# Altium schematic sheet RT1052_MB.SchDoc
size 297 x 210 mm
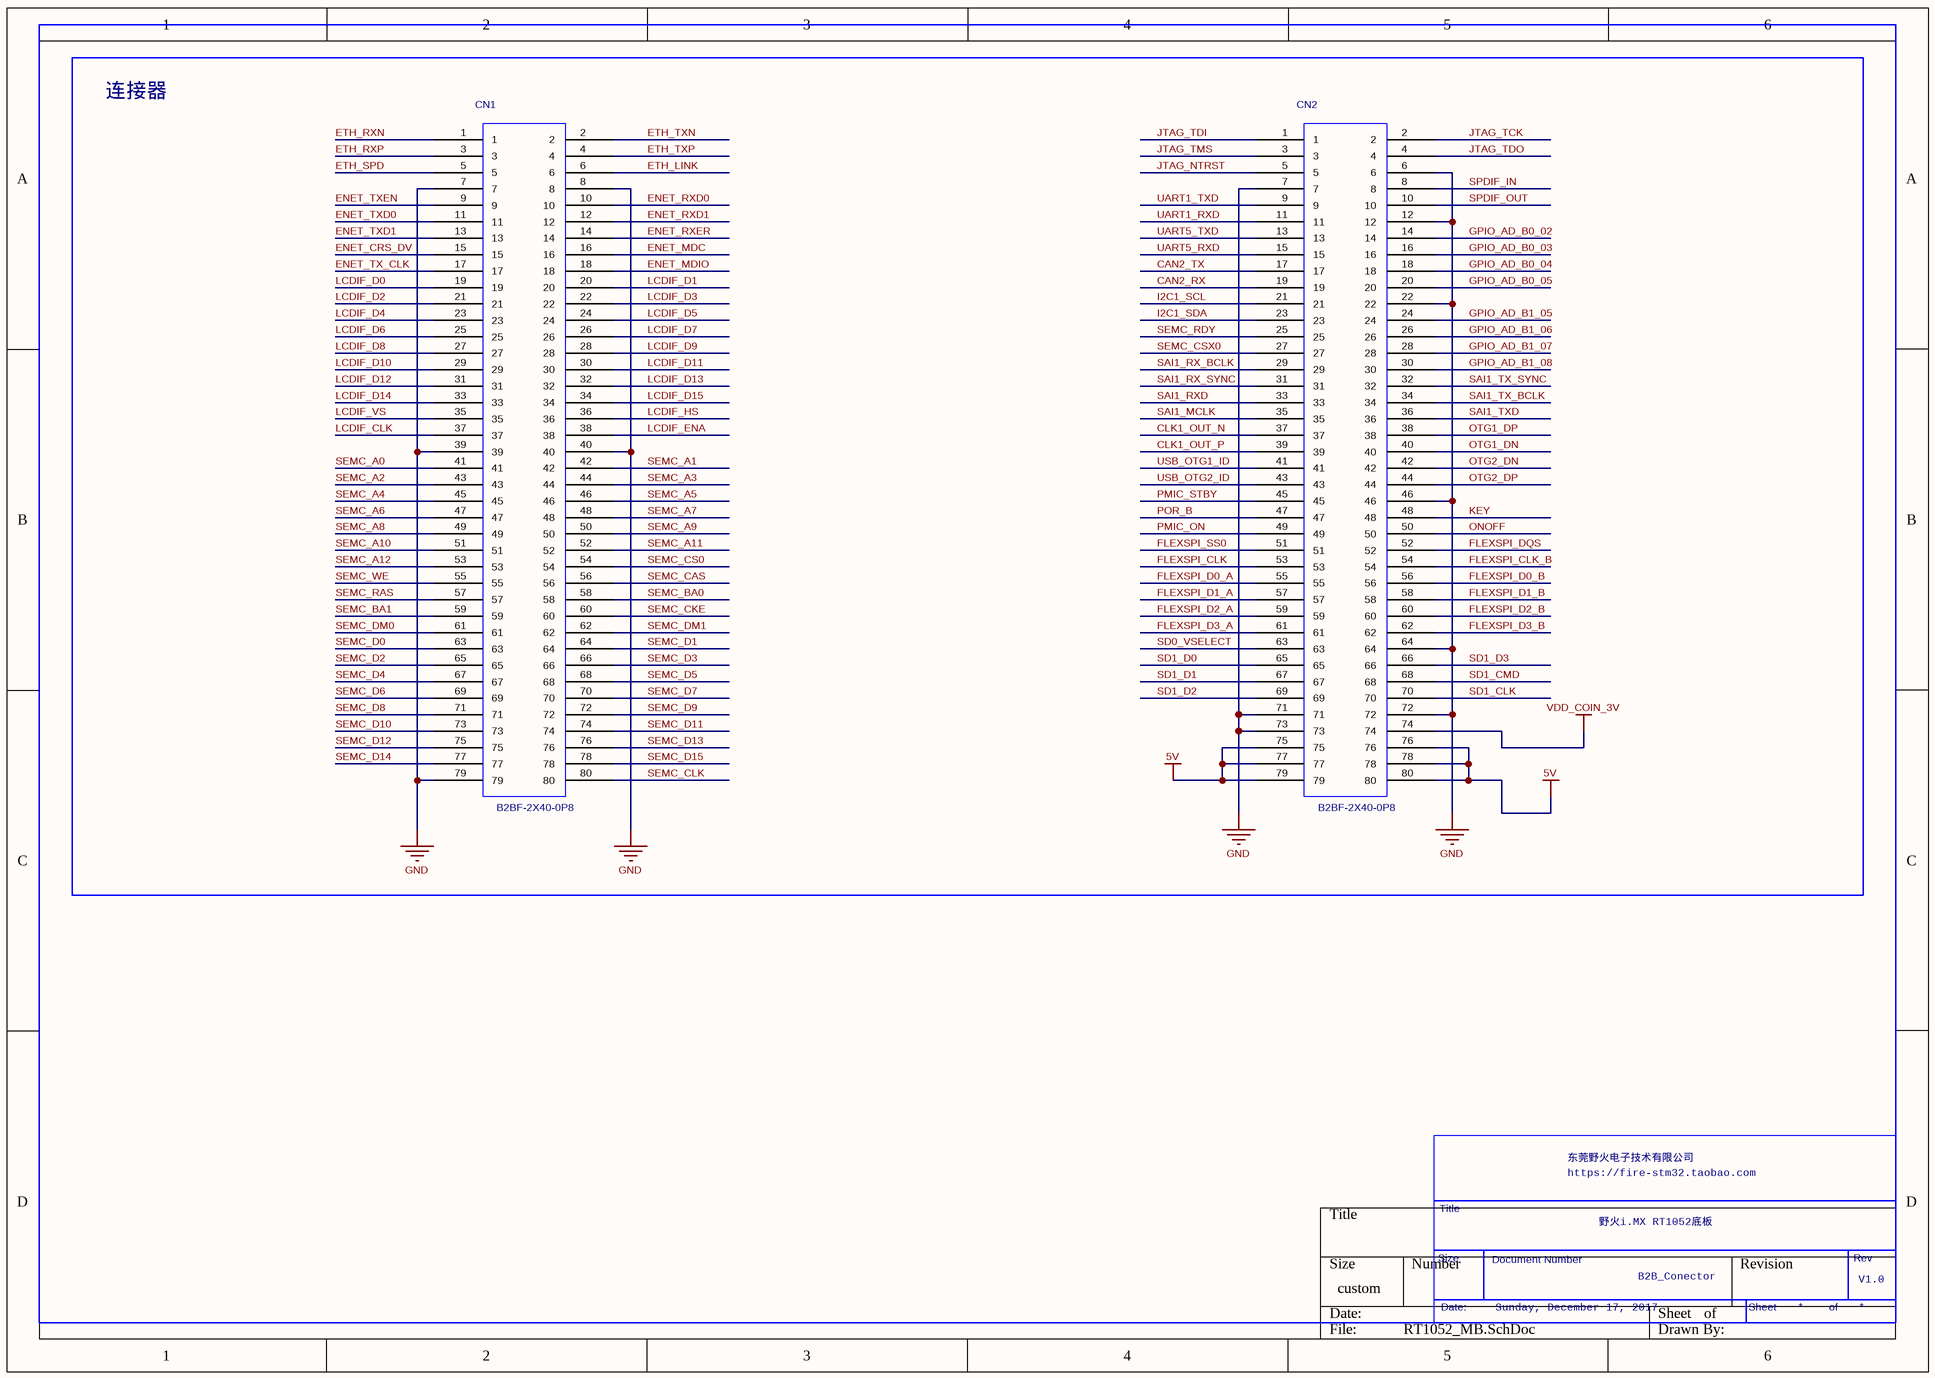
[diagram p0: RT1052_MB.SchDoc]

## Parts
CN1  value B2BF-2X40-0P8  [B2BF-2X40-0P8]  (hidden comment: B2B_2X40_0_8MM)
CN2  value B2BF-2X40-0P8  [B2BF-2X40-0P8]  (hidden comment: B2B_2X40_0_8MM)

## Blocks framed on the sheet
连接器: CN1 CN2

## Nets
5V: CN2.75 CN2.76 CN2.77 CN2.78 CN2.79 CN2.80
GND: CN1.7 CN1.8 CN1.39 CN1.40 CN1.79 CN2.6 CN2.7 CN2.12 CN2.22 CN2.46 CN2.64 CN2.71 CN2.72 CN2.73
VDD_COIN_3V: CN2.74
CAN2_RX: CN2.19
CAN2_TX: CN2.17
CLK1_OUT_N: CN2.37
CLK1_OUT_P: CN2.39
ENET_CRS_DV: CN1.15
ENET_MDC: CN1.16
ENET_MDIO: CN1.18
ENET_RXD0: CN1.10
ENET_RXD1: CN1.12
ENET_RXER: CN1.14
ENET_TX_CLK: CN1.17
ENET_TXD0: CN1.11
ENET_TXD1: CN1.13
ENET_TXEN: CN1.9
ETH_LINK: CN1.6
ETH_RXN: CN1.1
ETH_RXP: CN1.3
ETH_SPD: CN1.5
ETH_TXN: CN1.2
ETH_TXP: CN1.4
FLEXSPI_CLK: CN2.53
FLEXSPI_CLK_B: CN2.54
FLEXSPI_D0_A: CN2.55
FLEXSPI_D0_B: CN2.56
FLEXSPI_D1_A: CN2.57
FLEXSPI_D1_B: CN2.58
FLEXSPI_D2_A: CN2.59
FLEXSPI_D2_B: CN2.60
FLEXSPI_D3_A: CN2.61
FLEXSPI_D3_B: CN2.62
FLEXSPI_DQS: CN2.52
FLEXSPI_SS0: CN2.51
GPIO_AD_B0_02: CN2.14
GPIO_AD_B0_03: CN2.16
GPIO_AD_B0_04: CN2.18
GPIO_AD_B0_05: CN2.20
GPIO_AD_B1_05: CN2.24
GPIO_AD_B1_06: CN2.26
GPIO_AD_B1_07: CN2.28
GPIO_AD_B1_08: CN2.30
I2C1_SCL: CN2.21
I2C1_SDA: CN2.23
JTAG_NTRST: CN2.5
JTAG_TCK: CN2.2
JTAG_TDI: CN2.1
JTAG_TDO: CN2.4
JTAG_TMS: CN2.3
KEY: CN2.48
LCDIF_CLK: CN1.37
LCDIF_D0: CN1.19
LCDIF_D1: CN1.20
LCDIF_D2: CN1.21
LCDIF_D3: CN1.22
LCDIF_D4: CN1.23
LCDIF_D5: CN1.24
LCDIF_D6: CN1.25
LCDIF_D7: CN1.26
LCDIF_D8: CN1.27
LCDIF_D9: CN1.28
LCDIF_D10: CN1.29
LCDIF_D11: CN1.30
LCDIF_D12: CN1.31
LCDIF_D13: CN1.32
LCDIF_D14: CN1.33
LCDIF_D15: CN1.34
LCDIF_ENA: CN1.38
LCDIF_HS: CN1.36
LCDIF_VS: CN1.35
ONOFF: CN2.50
OTG1_DN: CN2.40
OTG1_DP: CN2.38
OTG2_DN: CN2.42
OTG2_DP: CN2.44
PMIC_ON: CN2.49
PMIC_STBY: CN2.45
POR_B: CN2.47
SAI1_MCLK: CN2.35
SAI1_RX_BCLK: CN2.29
SAI1_RX_SYNC: CN2.31
SAI1_RXD: CN2.33
SAI1_TX_BCLK: CN2.34
SAI1_TX_SYNC: CN2.32
SAI1_TXD: CN2.36
SD0_VSELECT: CN2.63
SD1_CLK: CN2.70
SD1_CMD: CN2.68
SD1_D0: CN2.65
SD1_D1: CN2.67
SD1_D2: CN2.69
SD1_D3: CN2.66
SEMC_A0: CN1.41
SEMC_A1: CN1.42
SEMC_A2: CN1.43
SEMC_A3: CN1.44
SEMC_A4: CN1.45
SEMC_A5: CN1.46
SEMC_A6: CN1.47
SEMC_A7: CN1.48
SEMC_A8: CN1.49
SEMC_A9: CN1.50
SEMC_A10: CN1.51
SEMC_A11: CN1.52
SEMC_A12: CN1.53
SEMC_BA0: CN1.58
SEMC_BA1: CN1.59
SEMC_CAS: CN1.56
SEMC_CKE: CN1.60
SEMC_CLK: CN1.80
SEMC_CS0: CN1.54
SEMC_CSX0: CN2.27
SEMC_D0: CN1.63
SEMC_D1: CN1.64
SEMC_D2: CN1.65
SEMC_D3: CN1.66
SEMC_D4: CN1.67
SEMC_D5: CN1.68
SEMC_D6: CN1.69
SEMC_D7: CN1.70
SEMC_D8: CN1.71
SEMC_D9: CN1.72
SEMC_D10: CN1.73
SEMC_D11: CN1.74
SEMC_D12: CN1.75
SEMC_D13: CN1.76
SEMC_D14: CN1.77
SEMC_D15: CN1.78
SEMC_DM0: CN1.61
SEMC_DM1: CN1.62
SEMC_RAS: CN1.57
SEMC_RDY: CN2.25
SEMC_WE: CN1.55
SPDIF_IN: CN2.8
SPDIF_OUT: CN2.10
UART1_RXD: CN2.11
UART1_TXD: CN2.9
UART5_RXD: CN2.15
UART5_TXD: CN2.13
USB_OTG1_ID: CN2.41
USB_OTG2_ID: CN2.43

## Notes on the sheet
- 东莞野火电子技术有限公司
- Title
- https://fire-stm32.taobao.com
- 野火i.MX RT1052底板
- Size
- Date:
- Document Number
- Sunday, December 17, 2017
- B2B_Conector
- Sheet
- of
- Rev
- V1.0

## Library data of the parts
CN1 CN2 = B2B_2X40_0_8MM: Source_Path: H:\NXP_RT1050\SCH\SCHLIB\YHSCHLIB.OLB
